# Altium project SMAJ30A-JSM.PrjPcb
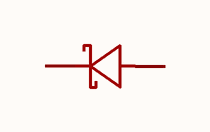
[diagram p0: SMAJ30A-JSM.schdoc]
1 sheet, 1 parts. Net scope: global (net labels, ports and power ports of the same name join across sheets).

## Sheet SMAJ30A-JSM.schdoc
size 127 x 101 mm

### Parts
D?  smaj30a-jsm  [SMA_L4.3-W2.6-LS5.2-RD-2]  (value not drawn)

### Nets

Not connected (* = marked no-connect by the designer): D? 1(C) 2(A)

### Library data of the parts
D? = smaj30a-jsm: 极性:单向;反向截止电压(Vrwm):30V;钳位电压:48.4V;峰值脉冲电流(Ipp):8.3A;峰值脉冲功率(Ppp):400W;击穿电压(VBR):36.8V;; Manufacturer: JSMSEMI(杰盛微); AddInBom: yes; ModelId: ab2d51b26b27441883b4afedb47aba08; ModelTransform: 200.787,102.362,0,0,0,0,0,0,0; Polarity: 单向; Reverse Stand-Off Voltage (Vrwm): 30V; Clamping Voltage: 48.4V; Peak Pulse Current (Ipp): 8.3A; Peak Pulse Power Dissipation (Ppp): 400W; Voltage - Breakdown: 36.8V; Reverse Leakage Current (Ir): 1uA; Number of Channels: 单路; Type: TVS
